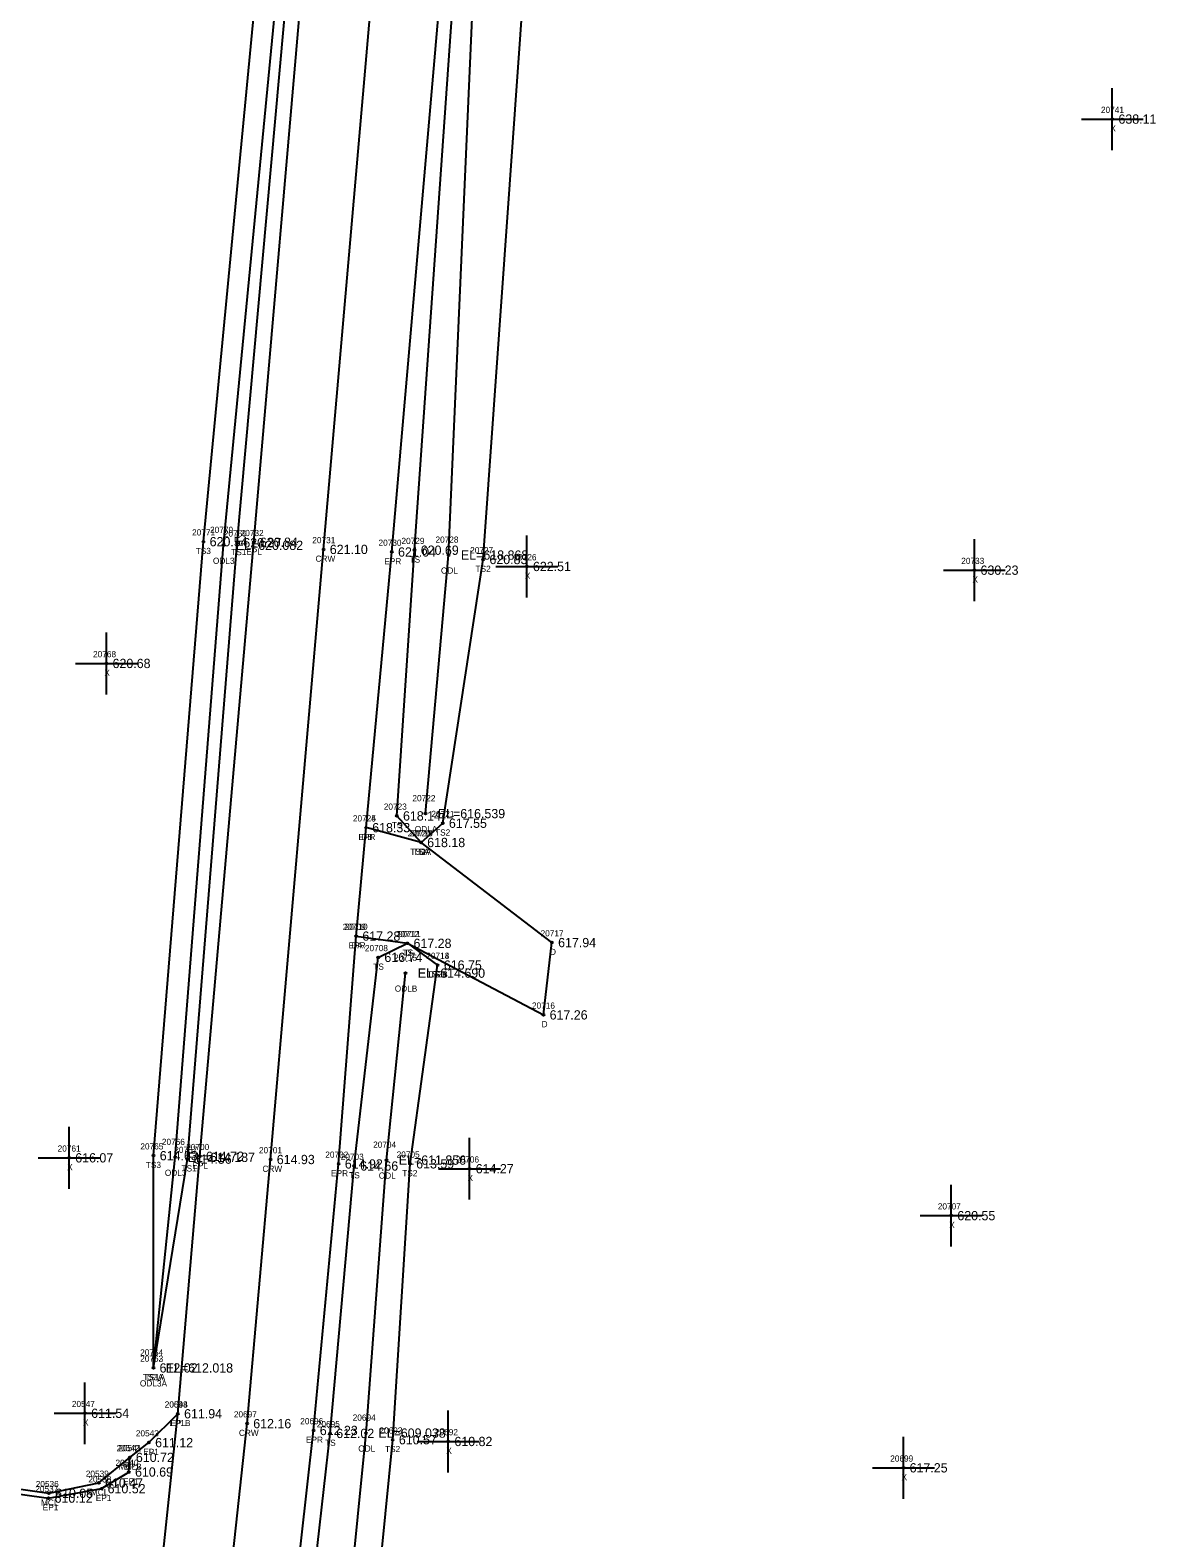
# Model space of a CAD drawing. Extents: x 1695443 to 1696344, y 1087542 to 1090645.
# Drawn here: x 1695796.6 to 1695978.6, y 1089958.1 to 1090201.9 of the extents above; entities that cross this region are included whole.
import ezdxf

# ---------------------------------------------------------------- set-up
doc = ezdxf.new("R2010")
doc.units = 0
for name, color, linetype in [('RD_DTM_BkLn1', 7, 'Continuous'), ('RD_DTM_BkLn2', 7, 'Continuous'), ('RD_DTM_BkLn_txCode', 7, 'Continuous'), ('RD_EX_Conc', 7, 'Continuous'), ('RD_EX_Conc_txCode', 7, 'Continuous'), ('RD_EX_Driveway', 7, 'Continuous'), ('RD_EX_Driveway_txCode', 7, 'Continuous'), ('RD_EX_H2O', 7, 'Continuous'), ('RD_EX_H2O_txCode', 7, 'Continuous'), ('RD_EX_Misc', 7, 'Continuous'), ('RD_EX_Misc_txCode', 7, 'Continuous'), ('RD_EX_Road', 7, 'Continuous'), ('RD_EX_Road_txCode', 7, 'Continuous'), ('RD_EX_TX_Conc_ELEV', 7, 'Continuous'), ('RD_EX_TX_Driveway_ELEV', 7, 'Continuous'), ('RD_EX_TX_H2O_ELEV', 7, 'Continuous'), ('RD_EX_TX_Misc_ELEV', 7, 'Continuous'), ('RD_EX_TX_Road_ELEV', 7, 'Continuous'), ('RD_HC_Survey_ELEV', 7, 'Continuous'), ('RD_HC_Survey_txCode', 7, 'Continuous'), ('RD_SMD_Locator', 7, 'Continuous')]:
    doc.layers.add(name, color=color, linetype=linetype)

msp = doc.modelspace()

# ---------------------------------------------------------------- linework, layer by layer
at = {"layer": 'RD_DTM_BkLn1'}
msp.add_lwpolyline([(1695813.78, 1089148.1), (1695785.55, 1089189.03), (1695758.89, 1089235.87), (1695740.64, 1089279.02), (1695725.17, 1089334.02), (1695718.27, 1089382.65), (1695717.41, 1089435.13), (1695722.03, 1089482.62), (1695732.64, 1089534.75), (1695759.85, 1089631.43), (1695787.11, 1089727.89), (1695798.89, 1089774.41), (1695810.31, 1089824.5), (1695818.49, 1089870.61), (1695825.85, 1089922.33), (1695831.69, 1089976.57), (1695835.49, 1090019.27), (1695844.06, 1090117.91), (1695852.56, 1090215.73), (1695861.78, 1090313.02), (1695870.8, 1090411.68), (1695879.44, 1090510.15), (1695888.04, 1090606.94)], dxfattribs=at)
at = {"layer": 'RD_DTM_BkLn2'}
for points in [[(1695816.55, 1089985.57), (1695822.06, 1090019.33), (1695830.08, 1090118.98), (1695839.03, 1090218.11), (1695848.5, 1090314.54), (1695858.08, 1090412.43), (1695866.47, 1090510.6), (1695872.4, 1090582.09), (1695875.15, 1090613.95)], [(1695859.8, 1090070.52), (1695855.89, 1090074.82), (1695858.76, 1090117.78), (1695865.52, 1090214.74), (1695874.78, 1090312.49), (1695883.57, 1090410.43), (1695892.81, 1090510.92), (1695900.47, 1090609.03)], [(1695859.8, 1090070.52), (1695863.31, 1090073.64), (1695869.86, 1090116.28), (1695876.76, 1090213.36), (1695888.73, 1090306.44), (1695897.16, 1090410.32), (1695906.91, 1090511.46), (1695912.67, 1090607.68)], [(1695816.55, 1089985.57), (1695816.58, 1090019.89), (1695824.64, 1090119.16), (1695834.2, 1090219.01), (1695837.98, 1090315.44), (1695847.83, 1090415.25), (1695858.61, 1090512.14), (1695862.95, 1090562.02), (1695858.41, 1090574.71)], [(1695831.14, 1089829.19), (1695828, 1089833.26), (1695832.64, 1089869.04), (1695838.97, 1089920.62), (1695845.1, 1089974.98), (1695848.98, 1090018.22), (1695852.88, 1090051.95), (1695857.59, 1090054.22), (1695862.49, 1090050.71)], [(1695831.14, 1089829.19), (1695836.38, 1089829.9), (1695844.06, 1089867.07), (1695849.86, 1089919.57), (1695855.22, 1089973.96), (1695858.02, 1090018.57), (1695862.49, 1090050.71)]]:
    msp.add_lwpolyline(points, dxfattribs=at)
at = {"layer": 'RD_EX_Conc'}
msp.add_lwpolyline([(1695745.81, 1089979.91), (1695747.12, 1089979.1), (1695750.44, 1089973.08), (1695752.24, 1089972.1), (1695799.67, 1089965.3), (1695807.74, 1089966.97), (1695812.72, 1089971.11)], dxfattribs=at)
at = {"layer": 'RD_EX_Driveway'}
msp.add_lwpolyline([(1695849.32, 1090055.39), (1695857.59, 1090054.22), (1695879.59, 1090042.65), (1695880.96, 1090054.34), (1695859.8, 1090070.52), (1695850.91, 1090072.92)], dxfattribs=at)
at = {"layer": 'RD_EX_H2O'}
for points in [[(1695860.52, 1090075.19), (1695864.26, 1090116.99), (1695868.56, 1090214.89), (1695876.96, 1090312.57), (1695885.5, 1090410.04), (1695895.53, 1090510.16), (1695905.88, 1090602.7), (1695906.59, 1090606.36)], [(1695816.55, 1089985.57), (1695820.09, 1090019.62), (1695827.87, 1090118.57), (1695837.5, 1090218.61), (1695845.63, 1090315.02), (1695854.17, 1090413.34), (1695863.46, 1090511.07), (1695865.97, 1090562.3), (1695858.41, 1090574.71)], [(1695832.12, 1089832.7), (1695838.13, 1089867.88), (1695845.5, 1089920.36), (1695850.91, 1089975.04), (1695854.21, 1090019.17), (1695857.28, 1090049.4)]]:
    msp.add_lwpolyline(points, dxfattribs=at)
at = {"layer": 'RD_EX_Misc'}
for p, q in [((1695971.52, 1090182.48), (1695971.52, 1090192.48)), ((1695966.52, 1090187.48), (1695976.52, 1090187.48)), ((1695876.89, 1090110.15), (1695876.89, 1090120.15)), ((1695949.23, 1090109.55), (1695949.23, 1090119.55)), ((1695871.89, 1090115.15), (1695881.89, 1090115.15)), ((1695944.23, 1090114.55), (1695954.23, 1090114.55)), ((1695808.95, 1090094.47), (1695808.95, 1090104.47)), ((1695803.95, 1090099.47), (1695813.95, 1090099.47)), ((1695802.92, 1090014.54), (1695802.92, 1090024.54)), ((1695867.64, 1090012.78), (1695867.64, 1090022.78)), ((1695797.92, 1090019.54), (1695807.92, 1090019.54)), ((1695862.64, 1090017.78), (1695872.64, 1090017.78)), ((1695945.48, 1090005.19), (1695945.48, 1090015.19)), ((1695940.48, 1090010.19), (1695950.48, 1090010.19)), ((1695805.49, 1089973.24), (1695805.49, 1089983.24)), ((1695800.49, 1089978.24), (1695810.49, 1089978.24)), ((1695864.2, 1089968.68), (1695864.2, 1089978.68)), ((1695859.2, 1089973.68), (1695869.2, 1089973.68)), ((1695937.77, 1089964.42), (1695937.77, 1089974.42)), ((1695932.77, 1089969.42), (1695942.77, 1089969.42))]:
    msp.add_line(p, q, dxfattribs=at)
at = {"layer": 'RD_EX_Road'}
for points in [[(1695813.78, 1089148.1), (1695805.56, 1089142.08), (1695776.44, 1089183.94), (1695749.27, 1089231.88), (1695730.49, 1089275.72), (1695714.87, 1089332.12), (1695707.87, 1089381.72), (1695706.58, 1089435.34), (1695711.58, 1089484.26), (1695722.15, 1089537.59), (1695749.04, 1089634.88), (1695776.11, 1089730.43), (1695788.13, 1089777.42), (1695798.89, 1089826.76), (1695807.1, 1089870.03), (1695814.71, 1089923.3), (1695820.51, 1089978.16), (1695824.04, 1090019.79), (1695832.76, 1090119.06), (1695841.25, 1090216.76), (1695850.36, 1090314.41), (1695859.24, 1090411.82), (1695868.09, 1090511.63), (1695876.75, 1090608.38)], [(1695728.69, 1089383.6), (1695727.9, 1089434.83), (1695732.68, 1089480.1), (1695743.4, 1089531.84), (1695770.35, 1089628.36), (1695797.63, 1089725.22), (1695809.49, 1089772.37), (1695818.34, 1089811.57), (1695820.65, 1089823.41), (1695822.99, 1089835.26), (1695829.18, 1089869.37), (1695836.32, 1089920.97), (1695842.44, 1089975.46), (1695846.49, 1090018.55), (1695849.32, 1090055.39), (1695850.91, 1090072.92), (1695855.09, 1090117.49), (1695863.53, 1090214.93), (1695872.56, 1090312.44), (1695881.69, 1090410.78), (1695890.45, 1090509.3), (1695899.01, 1090605.4)], [(1695733.94, 1089974.49), (1695752.2, 1089971.18), (1695799.58, 1089964.52), (1695808.15, 1089966.05), (1695812.58, 1089968.74), (1695812.72, 1089971.11), (1695815.83, 1089973.5), (1695820.51, 1089978.16)]]:
    msp.add_lwpolyline(points, dxfattribs=at)
at = {"layer": 'RD_SMD_Locator'}
for centre in [(1695971.52, 1090187.48), (1695824.64, 1090119.16), (1695827.87, 1090118.57), (1695830.08, 1090118.98), (1695832.76, 1090119.06), (1695844.06, 1090117.91), (1695855.09, 1090117.49), (1695858.76, 1090117.78), (1695864.26, 1090116.99), (1695869.86, 1090116.28), (1695876.89, 1090115.15), (1695949.23, 1090114.55), (1695808.95, 1090099.47), (1695855.89, 1090074.82), (1695860.52, 1090075.19), (1695850.91, 1090072.92), (1695850.91, 1090072.92), (1695863.31, 1090073.64), (1695859.8, 1090070.52), (1695859.8, 1090070.52), (1695859.8, 1090070.52), (1695849.32, 1090055.39), (1695849.32, 1090055.39), (1695857.59, 1090054.22), (1695857.59, 1090054.22), (1695880.96, 1090054.34), (1695852.88, 1090051.95), (1695862.49, 1090050.71), (1695862.49, 1090050.71), (1695857.28, 1090049.4), (1695879.59, 1090042.65), (1695802.92, 1090019.54), (1695816.58, 1090019.89), (1695820.09, 1090019.62), (1695822.06, 1090019.33), (1695824.04, 1090019.79), (1695835.49, 1090019.27), (1695846.49, 1090018.55), (1695848.98, 1090018.22), (1695854.21, 1090019.17), (1695858.02, 1090018.57), (1695867.64, 1090017.78), (1695945.48, 1090010.19), (1695816.55, 1089985.57), (1695816.55, 1089985.57), (1695816.55, 1089985.57), (1695805.49, 1089978.24), (1695820.51, 1089978.16), (1695820.51, 1089978.16), (1695831.69, 1089976.57), (1695842.44, 1089975.46), (1695845.1, 1089974.98), (1695850.91, 1089975.04), (1695815.83, 1089973.5), (1695855.22, 1089973.96), (1695864.2, 1089973.68), (1695812.72, 1089971.11), (1695812.72, 1089971.11), (1695812.58, 1089968.74), (1695937.77, 1089969.42), (1695799.67, 1089965.3), (1695807.74, 1089966.97), (1695808.15, 1089966.05), (1695799.58, 1089964.52)]:
    msp.add_circle(centre, 0.15, dxfattribs=at)

# ---------------------------------------------------------------- texts
at = {"layer": 'RD_DTM_BkLn_txCode'}
for s, p in [('20771', (1695822.8, 1090120.16)), ('20769', (1695827.93, 1090119.98)), ('20729', (1695856.64, 1090118.78)), ('TS3', (1695823.39, 1090117.16)), ('TS1', (1695829.12, 1090116.98)), ('TS', (1695857.96, 1090115.78)), ('20727', (1695867.74, 1090117.28)), ('TS2', (1695868.62, 1090114.28)), ('20723', (1695853.78, 1090075.82)), ('20721', (1695861.48, 1090074.64)), ('TS', (1695855.1, 1090072.82)), ('20720', (1695857.65, 1090071.52)), ('20719', (1695857.97, 1090071.52)), ('TS2', (1695862.07, 1090071.64)), ('TS2A', (1695858.07, 1090068.52)), ('TSA', (1695858.52, 1090068.52)), ('20712', (1695855.76, 1090055.22)), ('20708', (1695850.73, 1090052.95)), ('TS', (1695856.8, 1090052.22)), ('20713', (1695860.65, 1090051.71)), ('20714', (1695860.65, 1090051.71)), ('TS', (1695852.09, 1090049.95)), ('TS2B', (1695860.77, 1090048.71)), ('TSB', (1695861.22, 1090048.71)), ('20765', (1695814.44, 1090020.89)), ('20767', (1695819.92, 1090020.33)), ('TS3', (1695815.33, 1090017.89)), ('20703', (1695846.82, 1090019.22)), ('20705', (1695855.86, 1090019.57)), ('TS1', (1695821.1, 1090017.33)), ('TS', (1695848.19, 1090016.22)), ('TS2', (1695856.77, 1090016.57)), ('20762', (1695814.41, 1089986.57)), ('20763', (1695814.41, 1089986.57)), ('TS3A', (1695814.82, 1089983.57)), ('TS1A', (1695815.1, 1089983.57)), ('20695', (1695842.96, 1089975.98)), ('20693', (1695853.08, 1089974.96)), ('TS', (1695844.3, 1089972.98)), ('TS2', (1695853.98, 1089971.96))]:
    msp.add_text(s, height=1, dxfattribs=at).set_placement(p)
at = {"layer": 'RD_EX_Conc_txCode'}
for s, p in [('20542', (1695810.6, 1089972.11)), ('MCLB', (1695810.95, 1089969.11)), ('20536', (1695797.53, 1089966.3)), ('20539', (1695805.62, 1089967.97)), ('MCL', (1695806.44, 1089964.97)), ('MCL', (1695798.38, 1089963.3))]:
    msp.add_text(s, height=1, dxfattribs=at).set_placement(p)
at = {"layer": 'RD_EX_Driveway_txCode'}
for s, p in [('20724', (1695848.79, 1090073.92)), ('20718', (1695857.97, 1090071.52)), ('DB', (1695850.13, 1090070.92)), ('D', (1695859.5, 1090068.52)), ('20710', (1695847.45, 1090056.39)), ('20711', (1695856.04, 1090055.22)), ('20717', (1695879.12, 1090055.34)), ('DA', (1695848.53, 1090053.39)), ('D', (1695857.28, 1090052.22)), ('D', (1695880.65, 1090052.34)), ('20716', (1695877.73, 1090043.65)), ('D', (1695879.29, 1090040.65))]:
    msp.add_text(s, height=1, dxfattribs=at).set_placement(p)
at = {"layer": 'RD_EX_H2O_txCode'}
for s, p in [('20770', (1695825.71, 1090120.57)), ('20728', (1695862.14, 1090118.99)), ('ODL3', (1695826.17, 1090115.57)), ('ODL', (1695863.02, 1090113.99)), ('20722', (1695858.41, 1090077.19)), ('ODLA', (1695858.79, 1090072.19)), ('20715', (1695855.44, 1090051.4)), ('ODLB', (1695855.56, 1090046.4)), ('20766', (1695817.92, 1090021.62)), ('20704', (1695852.06, 1090021.17)), ('ODL3', (1695818.4, 1090016.62)), ('ODL', (1695852.97, 1090016.17)), ('20764', (1695814.41, 1089987.57)), ('ODL3A', (1695814.37, 1089982.57)), ('20694', (1695848.76, 1089977.04)), ('ODL', (1695849.66, 1089972.04))]:
    msp.add_text(s, height=1, dxfattribs=at).set_placement(p)
at = {"layer": 'RD_EX_Misc_txCode'}
for s, p in [('20741', (1695969.69, 1090188.48)), ('X', (1695971.21, 1090185.48)), ('20726', (1695874.75, 1090116.15)), ('20733', (1695947.11, 1090115.55)), ('X', (1695876.57, 1090113.15)), ('X', (1695948.92, 1090112.55)), ('20768', (1695806.8, 1090100.47)), ('X', (1695808.63, 1090097.47)), ('20761', (1695801.07, 1090020.54)), ('X', (1695802.61, 1090017.54)), ('20706', (1695865.46, 1090018.78)), ('X', (1695867.32, 1090015.78)), ('20707', (1695943.32, 1090011.19)), ('X', (1695945.17, 1090008.19)), ('20547', (1695803.37, 1089979.24)), ('X', (1695805.17, 1089976.24)), ('20692', (1695862.05, 1089974.68)), ('X', (1695863.88, 1089971.68)), ('20699', (1695935.63, 1089970.42)), ('X', (1695937.46, 1089967.42))]:
    msp.add_text(s, height=1, dxfattribs=at).set_placement(p)
at = {"layer": 'RD_EX_Road_txCode'}
for s, p in [('20732', (1695830.65, 1090120.06)), ('20730', (1695852.93, 1090118.49)), ('EPL', (1695831.56, 1090117.06)), ('EPR', (1695853.86, 1090115.49)), ('20725', (1695848.79, 1090073.92)), ('EPR', (1695849.68, 1090070.92)), ('20709', (1695847.16, 1090056.39)), ('EPR', (1695848.09, 1090053.39)), ('20700', (1695821.85, 1090020.79)), ('EPL', (1695822.84, 1090017.79)), ('20702', (1695844.33, 1090019.55)), ('EPR', (1695845.26, 1090016.55)), ('20698', (1695818.37, 1089979.16)), ('20544', (1695818.39, 1089979.16)), ('EP1B', (1695819.12, 1089976.16)), ('EPL', (1695819.31, 1089976.16)), ('20696', (1695840.28, 1089976.46)), ('20543', (1695813.71, 1089974.5)), ('20541', (1695810.88, 1089972.11)), ('EP1', (1695814.91, 1089971.5)), ('EPR', (1695841.21, 1089973.46)), ('20540', (1695810.42, 1089969.74)), ('EP1', (1695811.8, 1089969.11)), ('20538', (1695806.04, 1089967.05)), ('EP1', (1695811.66, 1089966.74)), ('20537', (1695797.46, 1089965.52)), ('EP1', (1695807.23, 1089964.05)), ('EP1', (1695798.66, 1089962.52))]:
    msp.add_text(s, height=1, dxfattribs=at).set_placement(p)
at = {"layer": 'RD_EX_TX_Conc_ELEV'}
for s, p in [('610.72', (1695813.72, 1089970.36)), ('610.47', (1695808.74, 1089966.22)), ('610.05', (1695800.67, 1089964.55))]:
    msp.add_text(s, height=1.5, dxfattribs=at).set_placement(p)
at = {"layer": 'RD_EX_TX_Driveway_ELEV'}
for s, p in [('618.33', (1695851.91, 1090072.17)), ('618.18', (1695860.8, 1090069.77)), ('617.28', (1695850.32, 1090054.64)), ('617.28', (1695858.59, 1090053.47)), ('617.94', (1695881.96, 1090053.59)), ('617.26', (1695880.59, 1090041.9))]:
    msp.add_text(s, height=1.5, dxfattribs=at).set_placement(p)
at = {"layer": 'RD_EX_TX_H2O_ELEV'}
for s, p in [('EL=620.082', (1695829.87, 1090117.82)), ('EL=618.868', (1695866.26, 1090116.24)), ('EL=616.539', (1695862.52, 1090074.44)), ('EL=614.690', (1695859.28, 1090048.65)), ('EL=614.187', (1695822.09, 1090018.87)), ('EL=611.856', (1695856.21, 1090018.42)), ('EL=612.018', (1695818.55, 1089984.82)), ('EL=609.038', (1695852.91, 1089974.29))]:
    msp.add_text(s, height=1.5, dxfattribs=at).set_placement(p)
at = {"layer": 'RD_EX_TX_Misc_ELEV'}
for s, p in [('638.11', (1695972.52, 1090186.73)), ('620.54', (1695825.64, 1090118.41)), ('620.37', (1695831.08, 1090118.23)), ('620.69', (1695859.76, 1090117.03)), ('620.83', (1695870.86, 1090115.53)), ('622.51', (1695877.89, 1090114.4)), ('630.23', (1695950.23, 1090113.8)), ('620.68', (1695809.95, 1090098.72)), ('618.14', (1695856.89, 1090074.07)), ('617.55', (1695864.31, 1090072.89)), ('618.18', (1695860.8, 1090069.77)), ('618.18', (1695860.8, 1090069.77)), ('617.28', (1695858.59, 1090053.47)), ('616.74', (1695853.88, 1090051.2)), ('616.75', (1695863.49, 1090049.96)), ('616.75', (1695863.49, 1090049.96)), ('616.07', (1695803.92, 1090018.79)), ('614.63', (1695817.58, 1090019.14)), ('614.56', (1695823.06, 1090018.58)), ('614.66', (1695849.98, 1090017.47)), ('613.59', (1695859.02, 1090017.82)), ('614.27', (1695868.64, 1090017.03)), ('620.55', (1695946.48, 1090009.44)), ('612.02', (1695817.55, 1089984.82)), ('612.02', (1695817.55, 1089984.82)), ('611.54', (1695806.49, 1089977.49)), ('612.02', (1695846.1, 1089974.23)), ('610.57', (1695856.22, 1089973.21)), ('610.82', (1695865.2, 1089972.93)), ('617.25', (1695938.77, 1089968.67))]:
    msp.add_text(s, height=1.5, dxfattribs=at).set_placement(p)
at = {"layer": 'RD_EX_TX_Road_ELEV'}
for s, p in [('620.84', (1695833.76, 1090118.31)), ('621.04', (1695856.09, 1090116.74)), ('618.33', (1695851.91, 1090072.17)), ('617.28', (1695850.32, 1090054.64)), ('614.72', (1695825.04, 1090019.04)), ('614.92', (1695847.49, 1090017.8)), ('611.94', (1695821.51, 1089977.41)), ('611.94', (1695821.51, 1089977.41)), ('612.23', (1695843.44, 1089974.71)), ('611.12', (1695816.83, 1089972.75)), ('610.72', (1695813.72, 1089970.36)), ('610.69', (1695813.58, 1089967.99)), ('610.12', (1695800.58, 1089963.77)), ('610.52', (1695809.15, 1089965.3))]:
    msp.add_text(s, height=1.5, dxfattribs=at).set_placement(p)
at = {"layer": 'RD_HC_Survey_ELEV'}
for s, p in [('621.10', (1695845.06, 1090117.16)), ('614.93', (1695836.49, 1090018.52)), ('612.16', (1695832.69, 1089975.82))]:
    msp.add_text(s, height=1.5, dxfattribs=at).set_placement(p)
at = {"layer": 'RD_HC_Survey_txCode'}
for s, p in [('20731', (1695842.23, 1090118.91)), ('CRW', (1695842.75, 1090115.91)), ('20701', (1695833.61, 1090020.27)), ('CRW', (1695834.17, 1090017.27)), ('20697', (1695829.55, 1089977.57)), ('CRW', (1695830.37, 1089974.57))]:
    msp.add_text(s, height=1, dxfattribs=at).set_placement(p)

doc.saveas('drawing.dxf')
